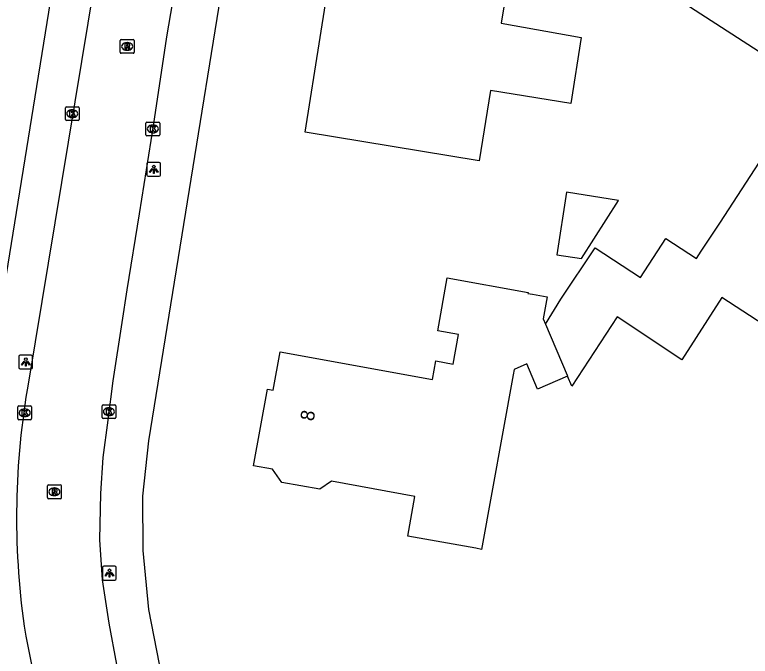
# Model space of a CAD drawing. Extents: x 161141 to 161601, y 381708 to 382245.
# Drawn here: x 161258.2 to 161311.4, y 381922.2 to 381968.7 of the extents above; entities that cross this region are included whole.
import ezdxf

# ---------------------------------------------------------------- set-up
doc = ezdxf.new("R2010")
doc.units = 0
for name, color, linetype in [('IMGEO_Kolk', 7, 'Continuous'), ('IMGEO_Lichtpunt', 7, 'Continuous'), ('IMGEO_Pand', 7, 'Continuous'), ('IMGEO_Pand_nummerreeks', 7, 'Continuous'), ('IMGEO_Rijbaan_lokaal_open', 7, 'Continuous'), ('IMGEO_Rioolput', 7, 'Continuous'), ('IMGEO_Voetpad_open', 7, 'Continuous')]:
    doc.layers.add(name, color=color, linetype=linetype)

msp = doc.modelspace()

# ---------------------------------------------------------------- linework, layer by layer
at = {"layer": 'IMGEO_Kolk'}
for p, q in [((161261.852, 381961.075), (161261.852, 381961.927)), ((161261.927, 381962.001), (161262.779, 381962.001)), ((161262.853, 381961.927), (161262.853, 381961.075)), ((161262.34, 381961.781), (161262.365, 381961.781)), ((161262.779, 381961.001), (161261.927, 381961.001)), ((161262.363, 381961.221), (161262.338, 381961.221)), ((161267.76, 381960.895), (161268.612, 381960.895)), ((161267.685, 381959.969), (161267.685, 381960.821)), ((161268.173, 381960.675), (161268.198, 381960.675)), ((161268.686, 381960.821), (161268.686, 381959.969)), ((161268.612, 381959.895), (161267.76, 381959.895)), ((161268.196, 381960.115), (161268.171, 381960.115)), ((161258.408, 381939.406), (161258.408, 381940.258)), ((161258.483, 381940.332), (161259.335, 381940.332)), ((161258.896, 381940.112), (161258.921, 381940.112)), ((161259.409, 381940.258), (161259.409, 381939.406)), ((161264.508, 381939.486), (161264.508, 381940.338)), ((161264.583, 381940.412), (161265.435, 381940.412)), ((161264.996, 381940.192), (161265.021, 381940.192)), ((161265.509, 381940.338), (161265.509, 381939.486)), ((161258.919, 381939.552), (161258.894, 381939.552)), ((161265.019, 381939.632), (161264.994, 381939.632)), ((161259.335, 381939.332), (161258.483, 381939.332)), ((161265.435, 381939.412), (161264.583, 381939.412))]:
    msp.add_line(p, q, dxfattribs=at)
for points in [[(161261.852, 381961.075), (161261.852, 381961.927)], [(161261.927, 381962.001), (161262.779, 381962.001)], [(161262.853, 381961.927), (161262.853, 381961.075)], [(161262.173, 381961.701), (161262.296, 381961.701), (161262.296, 381961.55), (161262.426, 381961.701), (161262.59, 381961.701), (161262.444, 381961.55), (161262.597, 381961.301), (161262.445, 381961.301), (161262.36, 381961.465), (161262.296, 381961.398), (161262.296, 381961.301), (161262.173, 381961.301), (161262.173, 381961.701)], [(161262.779, 381961.001), (161261.927, 381961.001)], [(161267.76, 381960.895), (161268.612, 381960.895)], [(161267.685, 381959.969), (161267.685, 381960.821)], [(161268.006, 381960.595), (161268.129, 381960.595), (161268.129, 381960.444), (161268.259, 381960.595), (161268.423, 381960.595), (161268.277, 381960.444), (161268.43, 381960.195), (161268.278, 381960.195), (161268.193, 381960.359), (161268.129, 381960.292), (161268.129, 381960.195), (161268.006, 381960.195), (161268.006, 381960.595)], [(161268.686, 381960.821), (161268.686, 381959.969)], [(161268.612, 381959.895), (161267.76, 381959.895)], [(161258.408, 381939.406), (161258.408, 381940.258)], [(161258.483, 381940.332), (161259.335, 381940.332)], [(161259.409, 381940.258), (161259.409, 381939.406)], [(161264.508, 381939.486), (161264.508, 381940.338)], [(161264.583, 381940.412), (161265.435, 381940.412)], [(161264.829, 381940.112), (161264.952, 381940.112), (161264.952, 381939.961), (161265.082, 381940.112), (161265.246, 381940.112), (161265.1, 381939.961), (161265.253, 381939.712), (161265.101, 381939.712), (161265.016, 381939.876), (161264.952, 381939.809), (161264.952, 381939.712), (161264.829, 381939.712), (161264.829, 381940.112)], [(161265.509, 381940.338), (161265.509, 381939.486)], [(161258.729, 381940.032), (161258.852, 381940.032), (161258.852, 381939.881), (161258.982, 381940.032), (161259.146, 381940.032), (161259, 381939.881), (161259.153, 381939.632), (161259.001, 381939.632), (161258.916, 381939.796), (161258.852, 381939.729), (161258.852, 381939.632), (161258.729, 381939.632), (161258.729, 381940.032)], [(161259.335, 381939.332), (161258.483, 381939.332)], [(161265.435, 381939.412), (161264.583, 381939.412)]]:
    msp.add_lwpolyline(points, dxfattribs=at)
for centre, start, end in [((161261.929, 381961.925), 91.552, 178.448), ((161261.929, 381961.925), 91.552, 178.448), ((161262.777, 381961.925), 1.552, 88.448), ((161262.777, 381961.925), 1.552, 88.448), ((161261.929, 381961.077), 181.552, 268.448), ((161261.929, 381961.077), 181.552, 268.448), ((161262.777, 381961.077), 271.552, 358.448), ((161262.777, 381961.077), 271.552, 358.448), ((161267.762, 381960.819), 91.552, 178.448), ((161267.762, 381960.819), 91.552, 178.448), ((161268.61, 381960.819), 1.552, 88.448), ((161268.61, 381960.819), 1.552, 88.448), ((161267.762, 381959.971), 181.552, 268.448), ((161267.762, 381959.971), 181.552, 268.448), ((161268.61, 381959.971), 271.552, 358.448), ((161268.61, 381959.971), 271.552, 358.448), ((161258.485, 381940.256), 91.552, 178.448), ((161258.485, 381940.256), 91.552, 178.448), ((161259.333, 381940.256), 1.552, 88.448), ((161259.333, 381940.256), 1.552, 88.448), ((161264.585, 381940.336), 91.552, 178.448), ((161264.585, 381940.336), 91.552, 178.448), ((161265.433, 381940.336), 1.552, 88.448), ((161265.433, 381940.336), 1.552, 88.448), ((161258.485, 381939.408), 181.552, 268.448), ((161258.485, 381939.408), 181.552, 268.448), ((161259.333, 381939.408), 271.552, 358.448), ((161259.333, 381939.408), 271.552, 358.448), ((161264.585, 381939.488), 181.552, 268.448), ((161264.585, 381939.488), 181.552, 268.448), ((161265.433, 381939.488), 271.552, 358.448), ((161265.433, 381939.488), 271.552, 358.448)]:
    msp.add_arc(centre, 0.0765, start, end, dxfattribs=at)
for centre, major_axis, ratio, start_param, end_param in [((161262.339, 381961.501), (-0.387, 0.002), 0.722429, 4.712389, 7.853982), ((161262.364, 381961.501), (-0.39, 0.002), 0.717154, 1.570796, 4.712389), ((161268.172, 381960.395), (-0.387, 0.002), 0.722429, 4.712389, 7.853982), ((161268.197, 381960.395), (-0.39, 0.002), 0.717154, 1.570796, 4.712389), ((161258.895, 381939.832), (-0.387, 0.002), 0.722429, 4.712389, 7.853982), ((161258.92, 381939.832), (-0.39, 0.002), 0.717154, 1.570796, 4.712389), ((161264.995, 381939.912), (-0.387, 0.002), 0.722429, 4.712389, 7.853982), ((161265.02, 381939.912), (-0.39, 0.002), 0.717154, 1.570796, 4.712389)]:
    msp.add_ellipse(centre, major_axis=major_axis, ratio=ratio, start_param=start_param, end_param=end_param, dxfattribs=at)
at = {"layer": 'IMGEO_Lichtpunt'}
for p, q in [((161267.752, 381957.864), (161267.752, 381957.057)), ((161267.752, 381957.864), (161267.752, 381957.057)), ((161268.654, 381957.959), (161267.846, 381957.959)), ((161268.654, 381957.959), (161267.846, 381957.959)), ((161268.748, 381957.057), (161268.748, 381957.864)), ((161268.748, 381957.057), (161268.748, 381957.864)), ((161267.846, 381956.963), (161268.654, 381956.963)), ((161267.846, 381956.963), (161268.654, 381956.963)), ((161258.485, 381943.913), (161258.485, 381943.106)), ((161258.485, 381943.913), (161258.485, 381943.106)), ((161259.387, 381944.008), (161258.579, 381944.008)), ((161259.387, 381944.008), (161258.579, 381944.008)), ((161259.481, 381943.106), (161259.481, 381943.913)), ((161259.481, 381943.106), (161259.481, 381943.913)), ((161258.579, 381943.012), (161259.387, 381943.012)), ((161258.579, 381943.012), (161259.387, 381943.012)), ((161264.541, 381928.618), (161264.541, 381927.811)), ((161264.541, 381928.618), (161264.541, 381927.811)), ((161265.443, 381928.713), (161264.635, 381928.713)), ((161265.443, 381928.713), (161264.635, 381928.713)), ((161265.537, 381927.811), (161265.537, 381928.618)), ((161265.537, 381927.811), (161265.537, 381928.618)), ((161264.635, 381927.717), (161265.443, 381927.717)), ((161264.635, 381927.717), (161265.443, 381927.717))]:
    msp.add_line(p, q, dxfattribs=at)
for points in [[(161268.126, 381957.528), (161268.165, 381957.5), (161267.977, 381957.238), (161267.939, 381957.265), (161268.126, 381957.528)], [(161268.228, 381957.48), (161268.275, 381957.48), (161268.275, 381957.158), (161268.228, 381957.158), (161268.228, 381957.48)], [(161268.338, 381957.5), (161268.376, 381957.527), (161268.563, 381957.265), (161268.524, 381957.237), (161268.338, 381957.5)], [(161258.859, 381943.577), (161258.898, 381943.549), (161258.71, 381943.287), (161258.672, 381943.314), (161258.859, 381943.577)], [(161258.961, 381943.529), (161259.008, 381943.529), (161259.008, 381943.207), (161258.961, 381943.207), (161258.961, 381943.529)], [(161259.071, 381943.549), (161259.109, 381943.576), (161259.296, 381943.314), (161259.257, 381943.286), (161259.071, 381943.549)], [(161264.915, 381928.282), (161264.954, 381928.254), (161264.766, 381927.992), (161264.728, 381928.019), (161264.915, 381928.282)], [(161265.017, 381928.234), (161265.064, 381928.234), (161265.064, 381927.912), (161265.017, 381927.912), (161265.017, 381928.234)], [(161265.127, 381928.254), (161265.165, 381928.281), (161265.352, 381928.019), (161265.313, 381927.991), (161265.127, 381928.254)]]:
    msp.add_lwpolyline(points, dxfattribs=at)
for centre in [(161268.251, 381957.662), (161258.984, 381943.711), (161265.04, 381928.416)]:
    msp.add_circle(centre, 0.0994, dxfattribs=at)
for centre, start, end in [((161267.846, 381957.864), 90, 180), ((161267.846, 381957.864), 90, 180), ((161268.654, 381957.864), 0, 90), ((161268.654, 381957.864), 0, 90), ((161267.846, 381957.057), 180, 270), ((161267.846, 381957.057), 180, 270), ((161268.654, 381957.057), 270, 0), ((161268.654, 381957.057), 270, 360), ((161258.579, 381943.913), 90, 180), ((161258.579, 381943.913), 90, 180), ((161259.387, 381943.913), 0, 90), ((161259.387, 381943.913), 0, 90), ((161258.579, 381943.106), 180, 270), ((161258.579, 381943.106), 180, 270), ((161259.387, 381943.106), 270, 0), ((161259.387, 381943.106), 270, 360), ((161264.635, 381928.618), 90, 180), ((161264.635, 381928.618), 90, 180), ((161265.443, 381928.618), 0, 90), ((161265.443, 381928.618), 0, 90), ((161264.635, 381927.811), 180, 270), ((161264.635, 381927.811), 180, 270), ((161265.443, 381927.811), 270, 0), ((161265.443, 381927.811), 270, 360)]:
    msp.add_arc(centre, 0.0946, start, end, dxfattribs=at)
at = {"layer": 'IMGEO_Pand'}
for points in [[(161291.811, 381958.087), (161279.219, 381960.153), (161281.395, 381973.911), (161294.018, 381971.914), (161293.408, 381968.055), (161299.194, 381967.02), (161298.451, 381962.239), (161292.636, 381963.173), (161291.811, 381958.087)], [(161296.607, 381946.251), (161297.721, 381948.068), (161300.204, 381951.783), (161303.481, 381949.642), (161305.314, 381952.447), (161307.532, 381950.998), (161307.878, 381951.537), (161309.224, 381953.565), (161312.409, 381958.477), (161314.316, 381957.241), (161314.709, 381957.847), (161317.744, 381955.877), (161317.332, 381955.241), (161317.942, 381954.845)], [(161297.43, 381951.283), (161299.225, 381951.001), (161301.894, 381955.216), (161298.141, 381955.806), (161297.43, 381951.283)], [(161298.211, 381942.48), (161296.04, 381941.544), (161295.252, 381943.372), (161294.338, 381942.978), (161294.265, 381942.576), (161291.973, 381929.937), (161291.557, 381930.012), (161286.637, 381930.904), (161287.158, 381933.774), (161281.107, 381934.871), (161280.27, 381934.291), (161277.515, 381934.791), (161276.858, 381935.739), (161275.471, 381935.99), (161276.48, 381941.554), (161276.904, 381941.479), (161277.407, 381944.254), (161288.438, 381942.254), (161288.68, 381943.588), (161289.928, 381943.362), (161290.314, 381945.493), (161288.805, 381945.766), (161289.501, 381949.607), (161295.347, 381948.546), (161295.334, 381948.474), (161295.664, 381948.413), (161296.72, 381948.236), (161296.441, 381946.64), (161296.607, 381946.251)], [(161312.965, 381947.06), (161312.408, 381946.208), (161309.369, 381948.193), (161306.469, 381943.662), (161301.803, 381946.771), (161298.521, 381941.748), (161298.211, 381942.48)], [(161296.607, 381946.251), (161298.176, 381942.561), (161298.211, 381942.48)]]:
    msp.add_lwpolyline(points, dxfattribs=at)
at = {"layer": 'IMGEO_Rijbaan_lokaal_open'}
for points in [[(161267.316, 381991.303), (161259.178, 381942.049)], [(161273.208, 381990.334), (161273.075, 381989.612), (161271.16, 381978.342), (161270.456, 381974.554), (161269.186, 381967.075), (161268.219, 381960.609), (161267.185, 381954.246), (161266.311, 381948.744), (161265.934, 381946.371), (161265.288, 381942.157), (161264.932, 381939.304), (161264.554, 381936.602), (161264.405, 381933.991), (161264.331, 381930.62), (161264.526, 381927.722), (161265, 381924.596), (161265.564, 381921.601), (161266.277, 381918.847), (161267.11, 381915.904), (161268.344, 381912.783), (161270.379, 381908.492), (161271.356, 381906.689)]]:
    msp.add_lwpolyline(points, dxfattribs=at)
for centre, radius, start, end in [((161315.125, 381932.225), 56.803, 170.0404, 187.9434), ((161329.155, 381936.504), 71.327, 189.79024, 199.2957)]:
    msp.add_arc(centre, radius, start, end, dxfattribs=at)
at = {"layer": 'IMGEO_Rioolput'}
for p, q in [((161265.827, 381965.947), (161265.827, 381966.799)), ((161265.902, 381966.873), (161266.754, 381966.873)), ((161266.828, 381966.799), (161266.828, 381965.947)), ((161266.315, 381966.653), (161266.34, 381966.653)), ((161266.754, 381965.873), (161265.902, 381965.873)), ((161266.338, 381966.093), (161266.313, 381966.093)), ((161260.56, 381933.683), (161260.56, 381934.535)), ((161260.635, 381934.609), (161261.487, 381934.609)), ((161261.048, 381934.389), (161261.073, 381934.389)), ((161261.561, 381934.535), (161261.561, 381933.683)), ((161261.071, 381933.829), (161261.046, 381933.829)), ((161261.487, 381933.609), (161260.635, 381933.609))]:
    msp.add_line(p, q, dxfattribs=at)
for points in [[(161265.827, 381965.947), (161265.827, 381966.799)], [(161265.902, 381966.873), (161266.754, 381966.873)], [(161266.828, 381966.799), (161266.828, 381965.947)], [(161266.416, 381966.571), (161266.164, 381966.573), (161266.164, 381966.173)], [(161266.164, 381966.173), (161266.288, 381966.173), (161266.288, 381966.335), (161266.299, 381966.335)], [(161266.342, 381966.492), (161266.288, 381966.492), (161266.288, 381966.411)], [(161266.288, 381966.411), (161266.34, 381966.411)], [(161266.346, 381966.306), (161266.417, 381966.173), (161266.557, 381966.173), (161266.492, 381966.299)], [(161266.754, 381965.873), (161265.902, 381965.873)], [(161260.56, 381933.683), (161260.56, 381934.535)], [(161260.635, 381934.609), (161261.487, 381934.609)], [(161261.149, 381934.307), (161260.897, 381934.309), (161260.897, 381933.909)], [(161261.075, 381934.228), (161261.021, 381934.228), (161261.021, 381934.147)], [(161261.561, 381934.535), (161261.561, 381933.683)], [(161260.897, 381933.909), (161261.021, 381933.909), (161261.021, 381934.071), (161261.032, 381934.071)], [(161261.021, 381934.147), (161261.073, 381934.147)], [(161261.079, 381934.042), (161261.15, 381933.909), (161261.29, 381933.909), (161261.225, 381934.035)], [(161261.487, 381933.609), (161260.635, 381933.609)]]:
    msp.add_lwpolyline(points, dxfattribs=at)
for centre, radius, start, end in [((161265.904, 381966.797), 0.0765, 91.552, 178.448), ((161265.904, 381966.797), 0.0765, 91.552, 178.448), ((161266.752, 381966.797), 0.0765, 1.552, 88.448), ((161266.752, 381966.797), 0.0765, 1.552, 88.448), ((161266.298, 381966.282), 0.0533, 26.0293, 88.6989), ((161266.324, 381966.6), 0.19, 274.7715, 282.9687), ((161266.348, 381966.396), 0.0964, 77.0061, 93.1865), ((161266.362, 381966.453), 0.0378, 276.6634, 79.6772), ((161266.415, 381966.461), 0.109, 350.3612, 89.416), ((161266.413, 381966.461), 0.112, 277.5842, 350.9817), ((161266.397, 381966.246), 0.108, 29.5134, 73.7905), ((161265.904, 381965.949), 0.0765, 181.552, 268.448), ((161265.904, 381965.949), 0.0765, 181.552, 268.448), ((161266.752, 381965.949), 0.0765, 271.552, 358.448), ((161266.752, 381965.949), 0.0765, 271.552, 358.448), ((161260.637, 381934.533), 0.0765, 91.552, 178.448), ((161260.637, 381934.533), 0.0765, 91.552, 178.448), ((161261.081, 381934.132), 0.0964, 77.0061, 93.1865), ((161261.095, 381934.189), 0.0378, 276.6634, 79.6772), ((161261.148, 381934.197), 0.109, 350.3612, 89.416), ((161261.485, 381934.533), 0.0765, 1.552, 88.448), ((161261.485, 381934.533), 0.0765, 1.552, 88.448), ((161260.637, 381933.685), 0.0765, 181.552, 268.448), ((161260.637, 381933.685), 0.0765, 181.552, 268.448), ((161261.031, 381934.018), 0.0533, 26.0293, 88.6989), ((161261.057, 381934.336), 0.19, 274.7715, 282.9687), ((161261.146, 381934.197), 0.112, 277.5842, 350.9817), ((161261.13, 381933.982), 0.108, 29.5134, 73.7905), ((161261.485, 381933.685), 0.0765, 271.552, 358.448), ((161261.485, 381933.685), 0.0765, 271.552, 358.448)]:
    msp.add_arc(centre, radius, start, end, dxfattribs=at)
for centre, major_axis, ratio, start_param, end_param in [((161266.314, 381966.373), (-0.387, 0.002), 0.722429, 4.712389, 7.853982), ((161266.339, 381966.373), (-0.39, 0.002), 0.717154, 1.570796, 4.712389), ((161261.047, 381934.109), (-0.387, 0.002), 0.722429, 4.712389, 7.853982), ((161261.072, 381934.109), (-0.39, 0.002), 0.717154, 1.570796, 4.712389)]:
    msp.add_ellipse(centre, major_axis=major_axis, ratio=ratio, start_param=start_param, end_param=end_param, dxfattribs=at)
at = {"layer": 'IMGEO_Voetpad_open'}
for points in [[(161256.038, 381940.3), (161256.817, 381945.219), (161264.337, 381991.77)], [(161276.309, 381989.126), (161276.14, 381989.025), (161267.873, 381937.797), (161267.435, 381933.784), (161267.467, 381929.855), (161267.871, 381925.589), (161268.634, 381921.624), (161269.796, 381917.444), (161271.533, 381912.948), (161272.783, 381910.378), (161277.045, 381903.774)], [(161370.462, 381928.258), (161276.309, 381989.126)]]:
    msp.add_lwpolyline(points, dxfattribs=at)

# ---------------------------------------------------------------- texts
at = {"layer": 'IMGEO_Pand_nummerreeks'}
msp.add_text('8', height=1, rotation=79.7271, dxfattribs=at).set_placement((161279.822, 381939.185))

doc.saveas('drawing.dxf')
